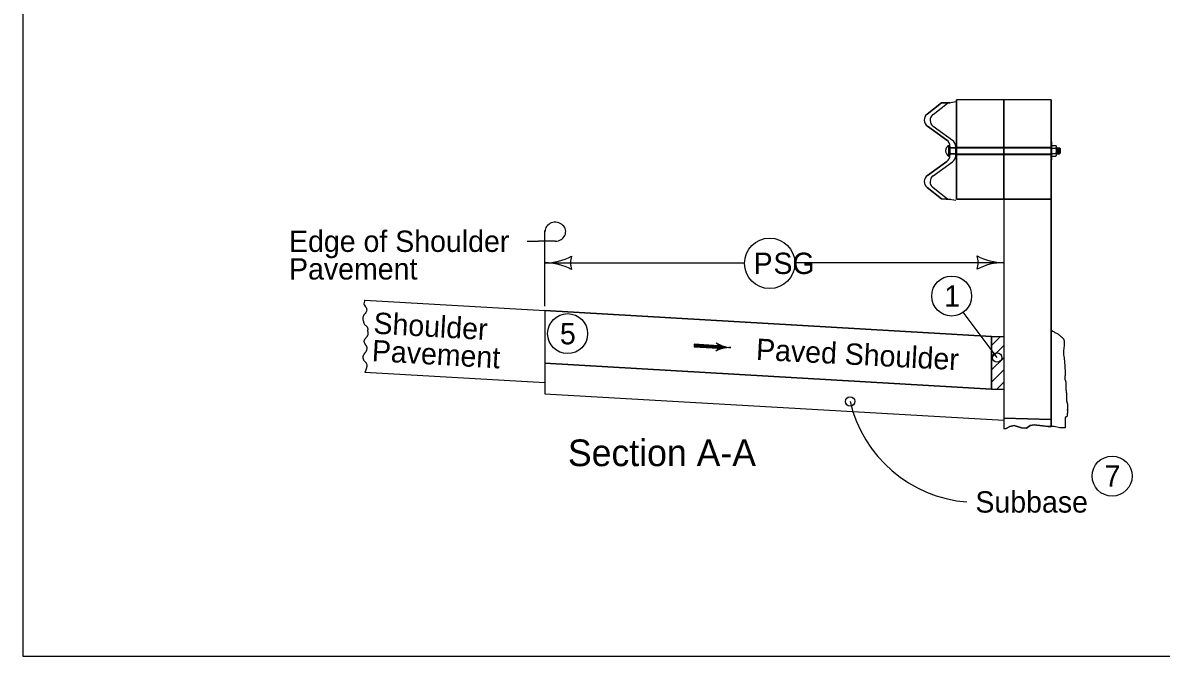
# Model space of a CAD drawing. Extents: x 10133 to 81668, y 7924 to 12229.
# Drawn here: x 10147 to 11002, y 10619 to 11094 of the extents above; entities that cross this region are included whole.
import ezdxf

# ---------------------------------------------------------------- set-up
doc = ezdxf.new("R2010")
doc.units = 0
for name, color, linetype in [('Cell', 7, 'Continuous'), ('dsnTextFinalPlan', 7, 'Continuous'), ('Level 1', 7, 'Continuous'), ('Level 12', 7, 'Continuous'), ('Level 21', 7, 'Continuous'), ('Level 4', 7, 'Continuous'), ('SheetText', 7, 'Continuous')]:
    doc.layers.add(name, color=color, linetype=linetype)

msp = doc.modelspace()

# ---------------------------------------------------------------- linework, layer by layer
at = {"layer": 'Cell'}
for p, q in [((10826.16, 11016.81), (10840.67, 11006.4)), ((10840.67, 10990.32), (10826.16, 10979.91)), ((10874.2, 10859.08), (10539.06, 10878.57)), ((10539.06, 10878.57), (10539.06, 10838.97)), ((10874.2, 10819.65), (10874.2, 10859.08)), ((10539.06, 10838.97), (10874.2, 10819.65))]:
    msp.add_line(p, q, dxfattribs=at)
for points in [[(10830.41, 11025.71), (10830.39, 11025.7), (10841.17, 11034.11), (10843.06, 11034.44), (10836.73, 11034.33), (10825.96, 11025.93)], [(10883.45, 11001.02), (10883.45, 11036.69), (10847.9, 11036.69), (10847.9, 11001.02), (10847.91, 11001.02), (10883.45, 11001.02)], [(10919, 11001.02), (10919, 11005.02), (10919, 11036.69), (10883.45, 11036.69), (10883.45, 11001.02), (10919, 11001.02)], [(10845.11, 11006.18), (10845.14, 11006.16), (10830.58, 11016.61), (10830.6, 11016.59)], [(10843.06, 11001.76), (10843.06, 11000.68), (10847.51, 11000.68), (10847.51, 11001.55), (10847.51, 11001.54)], [(10847.9, 11000.68), (10847.9, 10996.02), (10847.91, 10996.02), (10883.45, 10996.02), (10883.45, 11000.68), (10847.91, 11000.68), (10847.9, 11000.68)], [(10919, 10996.02), (10919, 11000.68), (10883.45, 11000.68), (10883.45, 10996.02), (10919, 10996.02)], [(10830.6, 10979.69), (10830.58, 10979.67), (10845.14, 10990.12), (10845.11, 10990.1)], [(10847.51, 10994.73), (10847.51, 10994.73), (10847.51, 10996.02), (10843.06, 10996.02), (10843.06, 10994.95), (10843.06, 10996.02), (10843.06, 10996.02), (10843.06, 10994.95)], [(10847.9, 10995.68), (10847.9, 10962.04), (10883.45, 10962.04), (10883.45, 10995.68), (10847.9, 10995.68)], [(10919, 10962.04), (10919, 10991.68), (10919, 10995.68), (10883.45, 10995.68), (10883.45, 10962.04), (10919, 10962.04)], [(10825.96, 10970.78), (10836.73, 10962.39), (10843.83, 10961.7), (10841.17, 10962.17), (10830.39, 10970.58), (10830.41, 10970.57)], [(10919, 10796.7), (10919, 10962.04), (10883.45, 10962.04), (10883.45, 10859.08), (10883.45, 10852.38), (10883.45, 10852.38), (10883.45, 10852.38), (10883.45, 10843.16), (10883.45, 10843.16), (10883.45, 10843.16), (10883.45, 10834.01), (10883.45, 10834.01), (10883.45, 10834.01), (10883.45, 10827.08), (10883.45, 10797.86), (10919, 10796.7)], [(10919, 10796.7), (10883.45, 10797.86), (10883.45, 10789.81), (10885.26, 10790.06), (10888.02, 10791.65), (10891.3, 10792.18), (10896.92, 10790.59), (10900.63, 10790.38), (10903.28, 10792.18), (10906.36, 10792.82), (10912.61, 10792.07), (10916.85, 10791.65), (10919, 10791.65), (10919, 10796.7)]]:
    msp.add_lwpolyline(points, dxfattribs=at)
msp.add_lwpolyline([(10847.51, 11000.68), (10843.06, 11000.68), (10843.06, 10997.22), (10843.06, 10998.36), (10843.06, 10996.02), (10847.51, 10996.02)], close=True, dxfattribs=at)
for centre, start, end in [((10829.44, 11021.44), 127.75002, 234.69086), ((10833.89, 11021.22), 127.75002, 234.69086), ((10837.39, 11001.76), 0, 54.69099), ((10841.83, 11001.54), 0, 54.69099), ((10837.39, 10994.95), 305.30901, 0), ((10841.83, 10994.73), 305.30901, 0), ((10829.44, 10975.27), 125.30914, 232.24998), ((10833.89, 10975.05), 125.30914, 232.24998)]:
    msp.add_arc(centre, 5.68, start, end, dxfattribs=at)
at = {"layer": 'dsnTextFinalPlan'}
for p, q in [((10825.96, 11025.93), (10836.73, 11034.33)), ((10830.39, 11025.7), (10841.17, 11034.11)), ((10836.73, 11034.33), (10843.06, 11034.44)), ((10841.17, 11034.11), (10847.51, 11035.23)), ((10919, 11036.69), (10847.9, 11036.69)), ((10847.9, 10962.04), (10847.9, 11036.69)), ((10883.45, 10962.04), (10883.45, 11036.69)), ((10919, 11036.69), (10919, 10791.65)), ((10840.67, 11006.4), (10826.16, 11016.81)), ((10845.14, 11006.16), (10830.58, 11016.61)), ((10842.29, 10994.29), (10842.29, 11002.38)), ((10842.29, 11000.68), (10847.72, 11000.68)), ((10843.06, 10994.95), (10843.06, 11001.76)), ((10843.06, 10994.95), (10843.06, 10998.36)), ((10843.06, 10998.36), (10843.06, 10994.95)), ((10843.24, 11000.68), (10847.9, 11000.68)), ((10847.51, 10998.14), (10847.51, 11001.55)), ((10847.91, 11001.02), (10919, 11001.02)), ((10847.91, 11000.68), (10919, 11000.68)), ((10919, 11004.99), (10919.68, 11004.99)), ((10919.68, 10991.66), (10919.68, 11004.99)), ((10919.68, 11002.36), (10922.64, 11002.36)), ((10919.68, 11000.34), (10922.64, 11000.34)), ((10923.01, 10995.29), (10923.01, 11001.35)), ((10923.01, 11000.65), (10925.38, 11000.65)), ((10923.9, 11000.65), (10923.9, 10995.99)), ((10924.64, 11000.65), (10924.64, 10995.99)), ((10925.38, 11000.65), (10925.83, 11000.12)), ((10925.38, 11000.65), (10925.38, 10995.99)), ((10925.83, 11000.12), (10925.83, 10996.52)), ((10826.16, 10979.91), (10840.67, 10990.32)), ((10830.58, 10979.67), (10845.14, 10990.12)), ((10842.29, 10996.02), (10847.9, 10996.02)), ((10847.51, 10994.73), (10847.51, 10998.14)), ((10847.51, 10998.14), (10847.51, 10994.73)), ((10847.9, 10995.68), (10919, 10995.68)), ((10847.91, 10996.02), (10919, 10996.02)), ((10919, 10991.66), (10919.68, 10991.66)), ((10919.68, 10996.3), (10922.64, 10996.3)), ((10919.68, 10994.28), (10922.64, 10994.28)), ((10923.01, 10995.99), (10925.38, 10995.99)), ((10925.83, 10996.52), (10925.38, 10995.99)), ((10836.73, 10962.39), (10825.96, 10970.78)), ((10841.17, 10962.17), (10830.39, 10970.58)), ((10843.83, 10961.7), (10836.73, 10962.39)), ((10847.51, 10961.05), (10841.17, 10962.17)), ((10883.45, 10962.04), (10847.9, 10962.04)), ((10883.45, 10962.04), (10883.45, 10789.81)), ((10403.92, 10886.42), (10539.06, 10878.57)), ((10539.06, 10878.57), (10539.06, 10824.55)), ((10539.06, 10878.57), (10874.2, 10859.08)), ((10874.2, 10852.33), (10880.94, 10859.08)), ((10874.2, 10852.33), (10880.94, 10859.08)), ((10874.2, 10852.33), (10880.94, 10859.08)), ((10874.2, 10852.33), (10880.94, 10859.08)), ((10874.2, 10859.08), (10883.43, 10859.08)), ((10874.2, 10859.08), (10874.2, 10819.65)), ((10874.2, 10843.15), (10883.43, 10852.38)), ((10874.2, 10843.15), (10883.43, 10852.38)), ((10874.2, 10843.15), (10883.43, 10852.38)), ((10874.2, 10843.15), (10883.43, 10852.38)), ((10929.05, 10852.31), (10929.05, 10852.31)), ((10874.2, 10819.65), (10539.06, 10838.97)), ((10874.2, 10833.92), (10883.43, 10843.16)), ((10874.2, 10833.92), (10883.43, 10843.16)), ((10874.2, 10833.92), (10883.43, 10843.16)), ((10874.2, 10833.92), (10883.43, 10843.16)), ((10403.95, 10832.41), (10539.06, 10824.55)), ((10874.2, 10824.69), (10883.43, 10833.93)), ((10539.06, 10824.55), (10539.06, 10816.13)), ((10874.2, 10819.65), (10883.43, 10819.65)), ((10878.29, 10819.65), (10883.43, 10824.79)), ((10539.06, 10816.13), (10883.45, 10796.28))]:
    msp.add_line(p, q, dxfattribs=at)
for points in [[(10922.71, 11000.35), (10922.78, 11000.39), (10922.85, 11000.49), (10922.94, 11000.71), (10922.99, 11001), (10923, 10999.05), (10922.94, 10999.56), (10922.89, 10999.93), (10922.77, 11000.26), (10922.71, 11000.34), (10922.76, 11000.35), (10922.87, 11000.5), (10922.96, 11000.72), (10922.98, 11000.88), (10922.98, 10999.34), (10922.91, 10999.83), (10922.85, 11000.1), (10922.75, 11000.32), (10922.78, 11000.33), (10922.92, 11000.55), (10922.96, 11000.7), (10922.96, 10999.6), (10922.77, 11000.31), (10922.94, 11000.59), (10922.94, 10999.74), (10922.79, 11000.3), (10922.92, 11000.52), (10922.92, 10999.88), (10922.81, 11000.28), (10922.9, 11000.46), (10922.9, 11000.04), (10922.83, 11000.27), (10922.89, 11000.38), (10922.89, 11000.18), (10922.86, 11000.25), (10922.87, 11000.3)], [(10923, 10995.62), (10922.95, 10995.88), (10922.9, 10996.06), (10922.82, 10996.21), (10922.7, 10996.3), (10922.78, 10996.4), (10922.86, 10996.62), (10922.92, 10996.94), (10923, 10997.69), (10923, 10995.61), (10922.98, 10995.75), (10922.93, 10995.97), (10922.86, 10996.18), (10922.74, 10996.29), (10922.78, 10996.38), (10922.84, 10996.53), (10922.94, 10997.03), (10922.98, 10997.41), (10922.98, 10995.8), (10922.95, 10995.92), (10922.9, 10996.09), (10922.78, 10996.29), (10922.83, 10996.46), (10922.91, 10996.8), (10922.96, 10997.12), (10922.96, 10995.96), (10922.92, 10996.09), (10922.81, 10996.28), (10922.85, 10996.5), (10922.9, 10996.76), (10922.94, 10996.93), (10922.94, 10996.06), (10922.88, 10996.17), (10922.83, 10996.29), (10922.92, 10996.74), (10922.92, 10996.14), (10922.85, 10996.28), (10922.9, 10996.57), (10922.9, 10996.22), (10922.86, 10996.29), (10922.88, 10996.39), (10922.88, 10996.32)], [(10929.52, 10828.47), (10929.46, 10828.2), (10929.46, 10828), (10929.46, 10827.81), (10929.46, 10827.61), (10929.46, 10827.41), (10929.46, 10827.22), (10929.46, 10826.93), (10929.46, 10826.73), (10929.56, 10826.44), (10929.66, 10826.14), (10929.85, 10825.95), (10929.85, 10825.75), (10929.95, 10825.56), (10929.95, 10825.36), (10929.95, 10825.17), (10930.05, 10825.07), (10930.05, 10824.87), (10930.05, 10824.68), (10930.05, 10824.48), (10930.05, 10824.29), (10930.05, 10824.09), (10930.05, 10823.8), (10930.05, 10823.51), (10930.05, 10823.31), (10930.05, 10823.02), (10930.05, 10822.82), (10930.05, 10822.63), (10930.14, 10822.53), (10930.14, 10822.33), (10930.14, 10822.14), (10930.14, 10821.94), (10930.14, 10821.75), (10930.14, 10821.55), (10930.14, 10821.36), (10930.14, 10821.16), (10930.14, 10820.97), (10930.14, 10820.77), (10930.14, 10820.58), (10930.14, 10820.38), (10930.14, 10820.18), (10930.14, 10819.99), (10930.14, 10819.79), (10930.14, 10819.6), (10930.14, 10819.4), (10930.14, 10819.21), (10930.14, 10819.01), (10930.24, 10818.91), (10930.24, 10818.72), (10930.24, 10818.52), (10930.34, 10818.43), (10930.34, 10818.23), (10930.34, 10818.03), (10930.44, 10817.94), (10930.44, 10817.74), (10930.44, 10817.55), (10930.44, 10817.35), (10930.44, 10817.06), (10930.53, 10816.76), (10930.53, 10816.57), (10930.53, 10816.37), (10930.53, 10816.18), (10930.53, 10815.98), (10930.53, 10815.79), (10930.53, 10815.59), (10930.53, 10815.4), (10930.53, 10815.2), (10930.53, 10815.01), (10930.53, 10814.81), (10930.53, 10814.62), (10930.53, 10814.42), (10930.53, 10814.22), (10930.53, 10814.03), (10930.53, 10813.83), (10930.53, 10813.64), (10930.53, 10813.44), (10930.53, 10813.25), (10930.53, 10813.05), (10930.53, 10812.86), (10930.53, 10812.66), (10930.53, 10812.47), (10930.53, 10812.27), (10930.53, 10812.08), (10930.53, 10811.88), (10930.53, 10811.68), (10930.53, 10811.49), (10930.53, 10811.29), (10930.53, 10811.1), (10930.63, 10811), (10930.63, 10810.71), (10930.63, 10810.51), (10930.73, 10810.32), (10930.83, 10810.02), (10930.83, 10809.83), (10930.93, 10809.73), (10930.93, 10809.53), (10931.02, 10809.44), (10931.12, 10809.34), (10931.12, 10809.14), (10931.12, 10808.95), (10931.12, 10808.75), (10931.22, 10808.66), (10931.22, 10808.46), (10931.22, 10808.26), (10931.22, 10808.07), (10931.22, 10807.87), (10931.22, 10807.68), (10931.22, 10807.48), (10931.22, 10807.29), (10931.22, 10807.09), (10931.22, 10806.9), (10931.22, 10806.7), (10931.22, 10806.51), (10931.22, 10806.31), (10931.22, 10806.12), (10931.22, 10805.92), (10931.22, 10805.72), (10931.22, 10805.53), (10931.22, 10805.33), (10931.22, 10805.14), (10931.22, 10804.94), (10931.22, 10804.75), (10931.22, 10804.55), (10931.22, 10804.36), (10931.22, 10804.16), (10931.22, 10803.97), (10931.22, 10803.77), (10931.22, 10803.77), (10931.22, 10804.06), (10931.22, 10804.26), (10931.22, 10804.45), (10931.22, 10804.26), (10931.22, 10804.06), (10931.22, 10803.87), (10931.22, 10803.67), (10931.22, 10803.48), (10931.22, 10803.28), (10931.22, 10803.09), (10931.22, 10802.89), (10931.22, 10802.7), (10931.22, 10802.5), (10931.22, 10802.3), (10931.22, 10802.11), (10931.22, 10801.91), (10931.22, 10801.72), (10931.22, 10801.52), (10931.12, 10801.43), (10931.12, 10801.23), (10931.12, 10801.03), (10931.12, 10800.84), (10931.12, 10800.64), (10931.12, 10800.45), (10931.12, 10800.25), (10931.12, 10800.06), (10931.12, 10799.86), (10931.12, 10799.67), (10931.12, 10799.47), (10931.02, 10799.37), (10930.93, 10799.18), (10930.83, 10799.08), (10930.73, 10798.98), (10930.63, 10798.88), (10930.44, 10798.79), (10930.24, 10798.79), (10930.14, 10798.69), (10930.05, 10798.59), (10929.95, 10798.49), (10929.75, 10798.4), (10929.66, 10798.3), (10929.66, 10798.1), (10929.56, 10798.01), (10929.56, 10797.81), (10929.56, 10797.61), (10929.56, 10797.42), (10929.56, 10790.6)], [(10929.69, 10790.61), (10925.54, 10790.48), (10921.41, 10791.65), (10916.85, 10791.65), (10912.61, 10792.07), (10906.36, 10792.82), (10903.28, 10792.18), (10900.63, 10790.38), (10896.92, 10790.59), (10891.3, 10792.18), (10888.02, 10791.65), (10885.26, 10790.06), (10883.45, 10789.81)]]:
    msp.add_lwpolyline(points, dxfattribs=at)
for centre, radius, start, end in [((10829.44, 11021.44), 5.68, 127.75002, 234.69086), ((10833.89, 11021.22), 5.68, 127.75002, 234.69086), ((10844.36, 10998.34), 4.54, 117.20289, 242.8461), ((10837.39, 11001.76), 5.68, 360, 54.69099), ((10841.83, 11001.54), 5.68, 360, 54.69099), ((10837.39, 10994.95), 5.68, 305.30901, 0), ((10841.83, 10994.73), 5.68, 305.30901, 0), ((10829.44, 10975.27), 5.68, 125.30914, 232.24998), ((10833.89, 10975.05), 5.68, 125.30914, 232.24998)]:
    msp.add_arc(centre, radius, start, end, dxfattribs=at)
for centre in [(10922.64, 11001.35), (10922.64, 10995.29)]:
    msp.add_ellipse(centre, major_axis=(0, -1.01), ratio=0.362258, start_param=6.283156, end_param=9.424748, dxfattribs=at)
for points in [[(10403.92, 10886.42), (10403.42, 10882.82), (10404.46, 10881.32), (10405.32, 10879.02), (10404.72, 10876.96), (10402.81, 10874.58), (10402.29, 10872.68), (10402.81, 10870.39), (10403.68, 10868.01), (10404.72, 10867.3), (10406.1, 10864.76), (10406.09, 10863.93)], [(10404.13, 10846.81), (10404.34, 10847.06), (10404.54, 10847.32), (10404.89, 10847.88), (10405.17, 10848.47), (10405.29, 10848.78), (10405.39, 10849.1), (10405.52, 10849.71), (10405.57, 10850.33), (10405.53, 10850.92), (10405.47, 10851.2), (10405.43, 10851.33), (10405.38, 10851.46), (10405.17, 10851.84), (10404.89, 10852.2), (10404.59, 10852.57), (10404.34, 10852.97), (10404.2, 10853.25), (10404.06, 10853.53), (10403.8, 10854.11), (10403.6, 10854.68), (10403.53, 10854.97), (10403.47, 10855.26), (10403.47, 10855.39), (10403.46, 10855.52), (10403.61, 10856.3), (10403.82, 10856.81), (10404.08, 10857.32), (10404.53, 10857.96), (10405.04, 10858.51), (10405.56, 10859.05), (10405.79, 10859.36), (10405.99, 10859.7), (10406.2, 10860.17), (10406.35, 10860.65), (10406.45, 10861.12), (10406.49, 10861.36), (10406.5, 10861.48), (10406.51, 10861.6), (10406.46, 10862.11), (10406.31, 10862.62), (10406.26, 10862.75), (10406.2, 10862.88), (10406.16, 10863), (10406.13, 10863.14), (10406.09, 10863.93)], [(10929.52, 10828.47), (10929.84, 10831.37), (10929.62, 10836.24), (10929.18, 10841.99), (10928.51, 10846.41), (10928.73, 10849.73), (10929.18, 10853.93), (10928.51, 10857.02), (10926.3, 10859.02), (10924.31, 10860.78), (10922.1, 10861.89), (10919.89, 10863.22), (10919, 10863.88)], [(10404.13, 10846.81), (10403.92, 10846.58), (10403.67, 10846.34), (10403.43, 10846.1), (10403.25, 10845.83), (10403.11, 10845.55), (10402.97, 10845.26), (10402.71, 10844.69), (10402.6, 10844.41), (10402.51, 10844.12), (10402.43, 10843.83), (10402.41, 10843.68), (10402.39, 10843.54), (10402.4, 10843.02), (10402.53, 10842.5), (10402.73, 10841.99), (10402.99, 10841.48), (10403.44, 10840.84), (10403.96, 10840.29), (10404.47, 10839.75), (10404.7, 10839.44), (10404.9, 10839.1), (10405.3, 10838.16), (10405.41, 10837.68), (10405.42, 10837.2), (10405.38, 10836.91), (10405.34, 10836.62), (10405.28, 10836.34), (10405.21, 10836.05), (10404.9, 10834.9), (10404.72, 10834.29), (10404.52, 10833.69), (10404.3, 10833.1), (10404.17, 10832.81), (10404.03, 10832.53), (10403.95, 10832.41)]]:
    msp.add_spline(points, degree=3, dxfattribs=at)
at = {"layer": 'Level 1'}
for p, q in [((10147.13, 12229.21), (10147.13, 10619.21)), ((10147.13, 10619.21), (13242.82, 10619.21))]:
    msp.add_line(p, q, dxfattribs=at)
at = {"layer": 'Level 12'}
for centre, radius in [((10844.39, 10889.37), 15), ((10556.11, 10861.18), 15), ((10878.51, 10843.25), 3.58), ((10964.83, 10754.32), 15)]:
    msp.add_circle(centre, radius, dxfattribs=at)
at = {"layer": 'Level 21'}
msp.add_circle((10556.11, 10861.18), 15, dxfattribs=at)
at = {"layer": 'Level 4'}
msp.add_line((10878.51, 10843.25), (10853.13, 10877.18), dxfattribs=at)
msp.add_circle((10768.2, 10810.29), 3.54, dxfattribs=at)
msp.add_circle((10768.2, 10810.29), 3.54, dxfattribs=at)
at = {"layer": 'SheetText'}
for p, q in [((10525.69, 10930.49), (10534.37, 10930.49)), ((10546.87, 10930.49), (10534.37, 10930.49)), ((10539.06, 10917.64), (10539.06, 10938.5)), ((10539.06, 10881.71), (10539.06, 10917.64)), ((10539.06, 10914.32), (10688.89, 10914.32)), ((10726.74, 10914.48), (10883.45, 10914.48)), ((10669.26, 10851.22), (10651.06, 10852.27)), ((10669.16, 10850.28), (10669.16, 10850.28)), ((10669.28, 10852.22), (10669.28, 10852.22))]:
    msp.add_line(p, q, dxfattribs=at)
for points in [[(10669.29, 10852.16), (10651.12, 10853.21), (10650.99, 10851.33), (10669.16, 10850.28), (10669.22, 10851.89), (10651.34, 10852.99), (10651.29, 10851.49), (10668.78, 10850.54), (10668.9, 10851.66), (10651.58, 10852.72), (10651.55, 10851.72), (10668.57, 10850.74), (10668.66, 10851.45), (10651.77, 10852.5), (10651.75, 10851.94), (10668.36, 10851)], [(10668.89, 10853.41), (10669.58, 10852.25), (10669.56, 10850.6), (10668.8, 10849.2), (10671.56, 10850.07), (10674.75, 10850.72), (10675.65, 10850.86), (10673.41, 10851.4), (10670.18, 10852.63), (10669.23, 10853.17), (10669.36, 10849.65), (10674.3, 10850.87), (10669.67, 10852.45), (10669.68, 10850.03), (10673.08, 10850.96), (10670.08, 10851.82), (10669.85, 10850.44), (10672, 10850.94), (10670.42, 10851.45), (10670.28, 10850.79), (10671.07, 10850.95)]]:
    msp.add_lwpolyline(points, dxfattribs=at)
msp.add_circle((10707.82, 10913.92), 18.93, dxfattribs=at)
for centre, radius, start, end in [((10539.06, 10956.82), 42.5, 270, 298.07249), ((10539.06, 10871.82), 42.5, 61.92751, 90), ((10574.7, 10914.32), 16.42, 162.26665, 197.73335), ((10847.82, 10914.48), 16.42, 342.26665, 17.73335), ((10883.45, 10956.98), 42.5, 241.92751, 270), ((10883.45, 10871.98), 42.5, 90, 118.07249), ((10863.43, 10832.41), 97.76, 193.07698, 265.55799)]:
    msp.add_arc(centre, radius, start, end, dxfattribs=at)
for centre, major_axis, start_param, end_param in [((10546.87, 10937.63), (-7.81, 0), 1.570796, 6.283185), ((10665.5, 10851.43), (3.88, 0), 5.202895, 7.237436), ((10680.56, 10870.86), (-22.17, 0), 0.954258, 1.478381), ((10677.77, 10830.44), (22.17, 0), 1.537172, 2.061295)]:
    msp.add_ellipse(centre, major_axis=major_axis, ratio=0.913811, start_param=start_param, end_param=end_param, dxfattribs=at)

# ---------------------------------------------------------------- texts
at = {"layer": 'Level 12'}
for s, p in [('1', (10838.77, 10881.37)), ('5', (10550.34, 10853.18)), ('7', (10959.13, 10746.32))]:
    msp.add_text(s, height=16, dxfattribs=at).set_placement(p)
at = {"layer": 'SheetText'}
for s, height, p in [('Edge of Shoulder ', 16, (10347, 10922.49)), ('P', 16, (10695.69, 10905.92)), ('SG', 16, (10710.61, 10905.92)), ('Pavement', 16, (10347, 10901.78)), ('Section A-A', 20, (10556.32, 10761.79)), ('Subbase', 16, (10862.21, 10726.94))]:
    msp.add_text(s, height=height, dxfattribs=at).set_placement(p)
for s, rotation, p in [('Shoulder', 356.73462, (10410.05, 10861.25)), ('Pavement', 356.73462, (10408.87, 10840.58)), ('Paved Shoulder ', 357.0678, (10697.28, 10841.58))]:
    msp.add_text(s, height=16, rotation=rotation, dxfattribs=at).set_placement(p)

doc.saveas('drawing.dxf')
